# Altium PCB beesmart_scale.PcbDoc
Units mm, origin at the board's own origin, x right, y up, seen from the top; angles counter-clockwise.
Board outline 20 x 50.5 mm, 2 copper layers (Top Layer, Bottom Layer); 16 components, 17 nets, 63 pads, 10 vias.
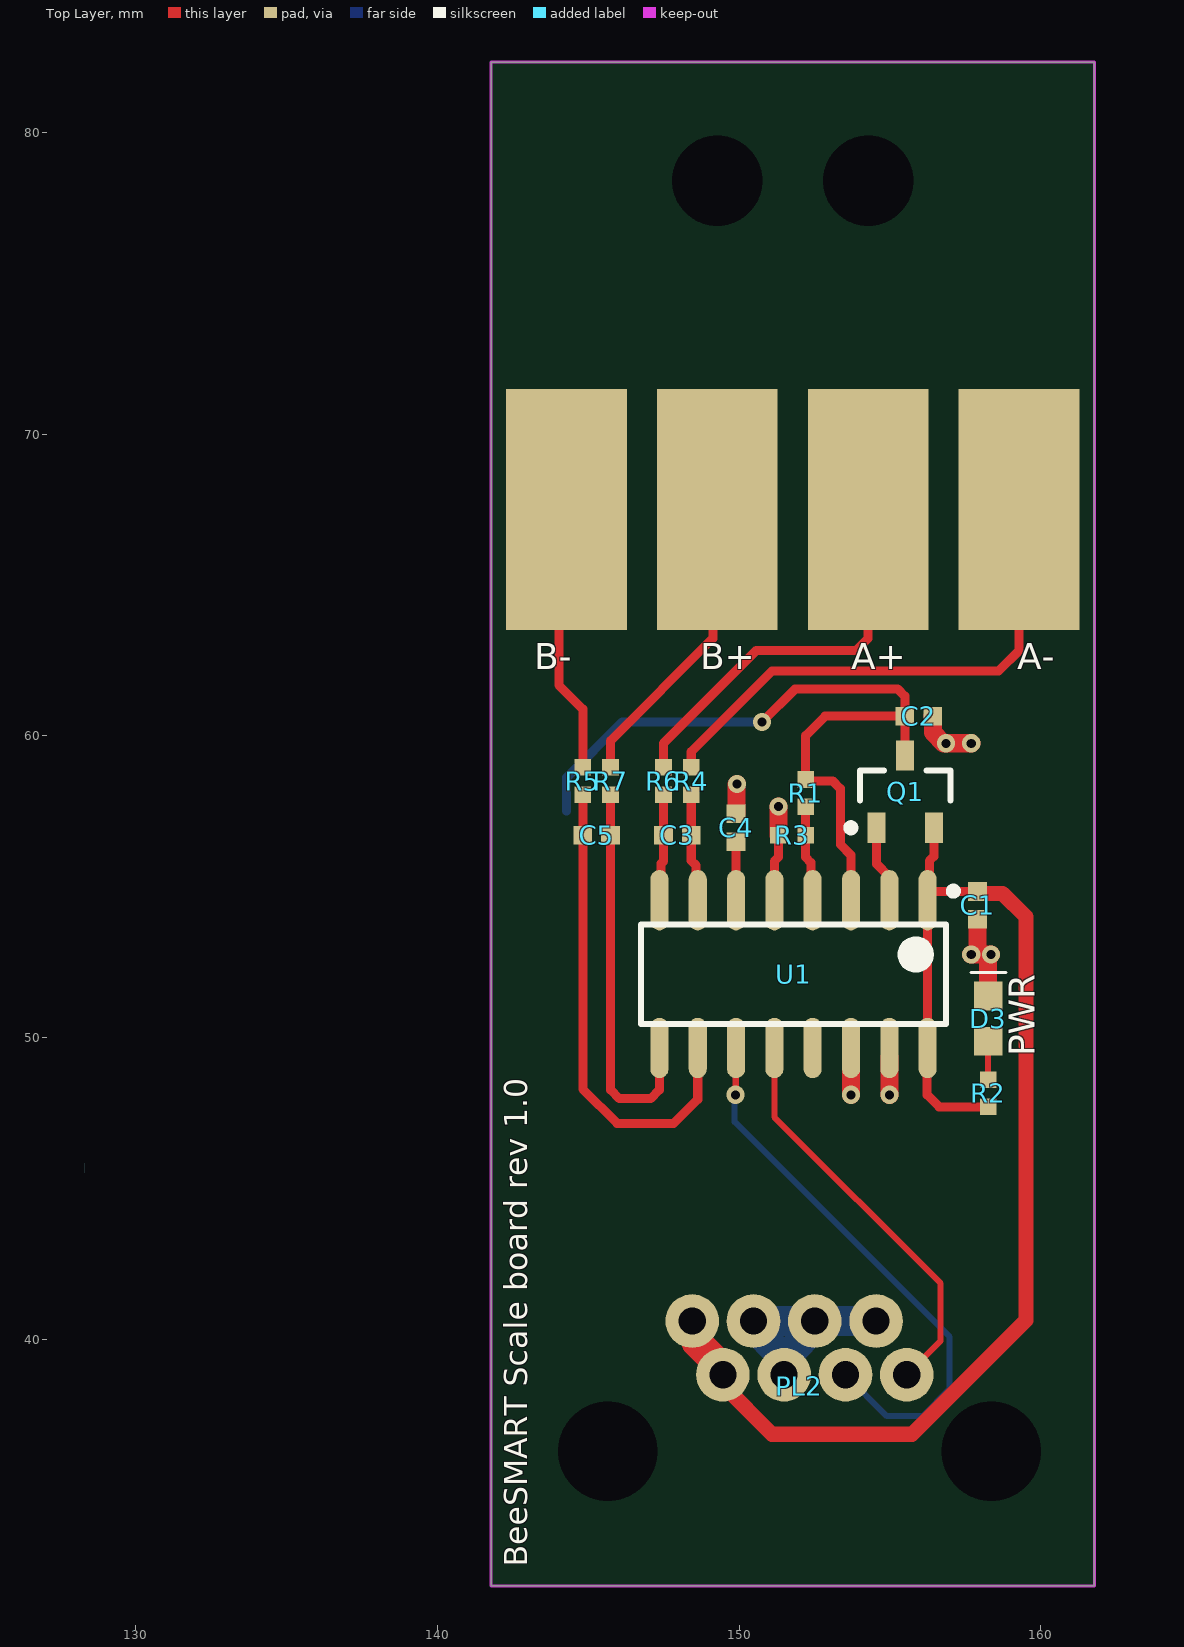
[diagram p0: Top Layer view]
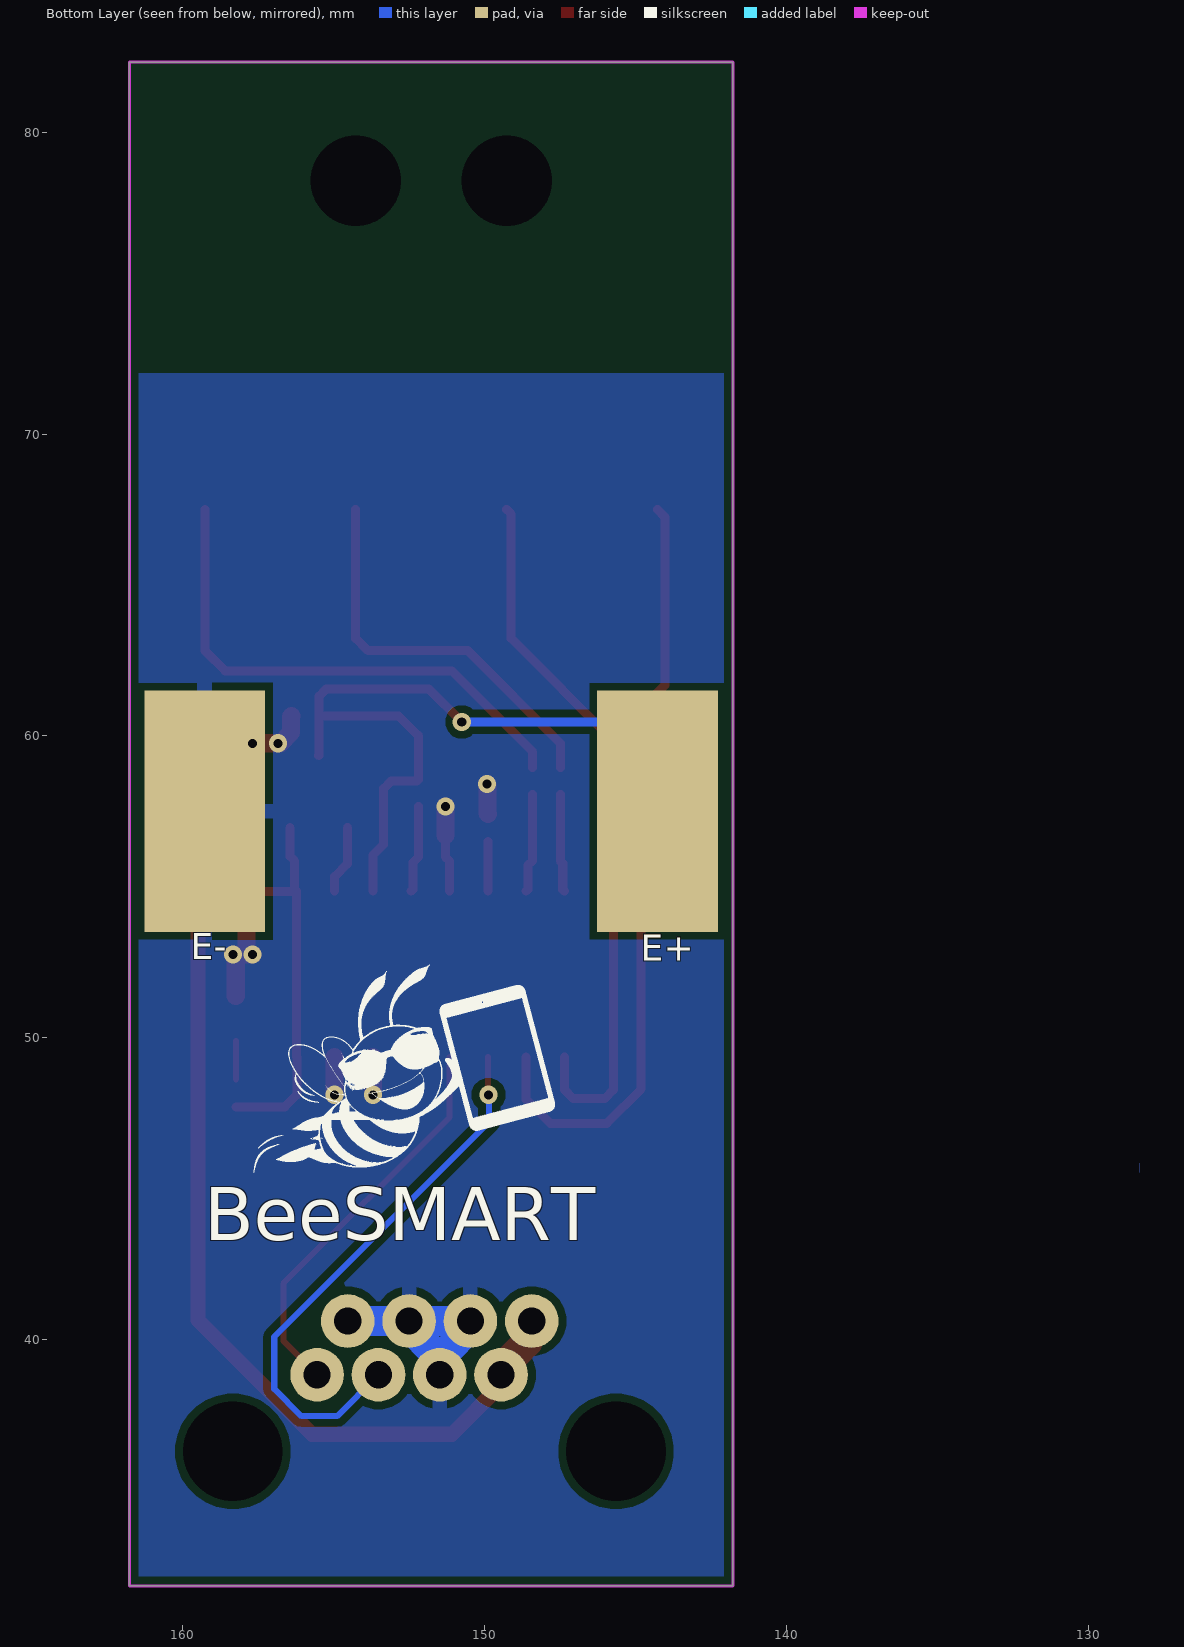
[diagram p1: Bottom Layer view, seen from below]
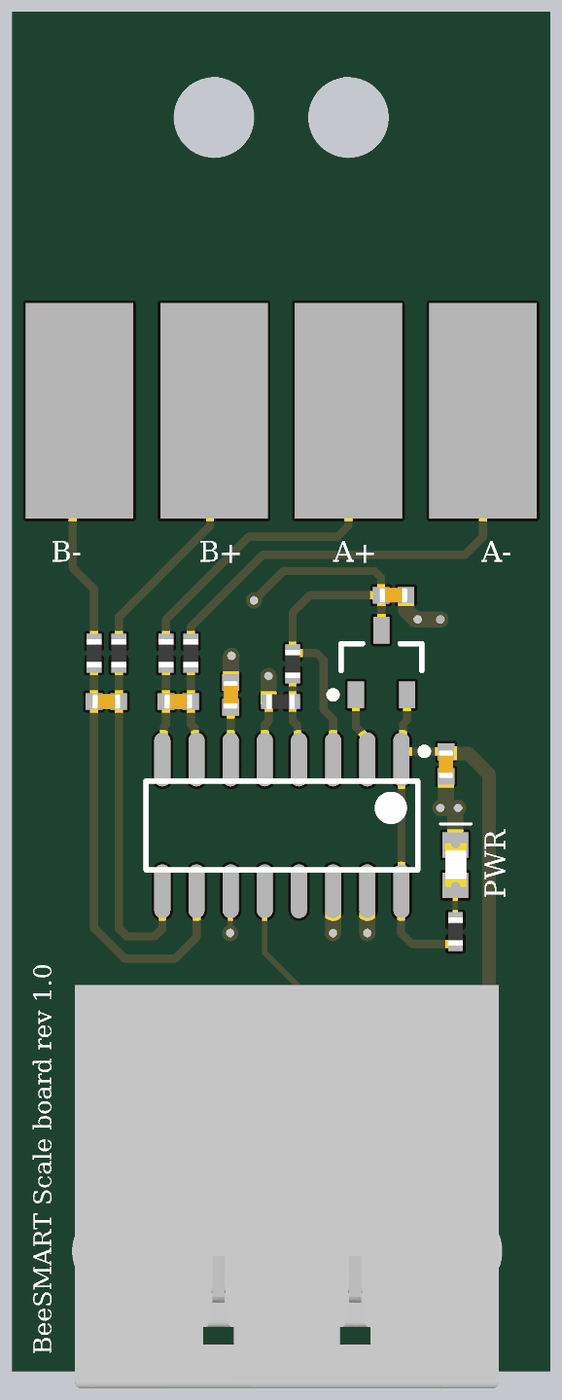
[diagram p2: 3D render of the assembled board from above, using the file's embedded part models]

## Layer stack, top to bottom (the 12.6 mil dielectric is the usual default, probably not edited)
Top Solder: solder mask 0.0102, Solder Resist, Dk 3.5
Top Layer: signal copper 0.0356
Dielectric 1: dielectric 0.32, FR-4, Dk 4.8
Bottom Layer: signal copper 0.0356
Bottom Solder: solder mask 0.0102, Solder Resist, Dk 3.5

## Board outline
141.775,31.825 161.775,31.825 161.775,82.325 141.775,82.325

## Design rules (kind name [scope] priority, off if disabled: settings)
Clearance [All] p1: gap=0.254 ignorepadtopadclearanceinfootprint=FALSE except(0: Arc-Hole Track-Hole SMDPad-Hole THPad-Hole Via-Hole Fill-Hole Poly-Hole Region-Hole Text-Hole; 0.2: Arc-SMDPad Arc-THPad Track-SMDPad Track-THPad SMDPad-SMDPad SMDPad-THPad)
PlaneConnect [All] p1: planeconnectstyle=Relief reliefexpansion=0.508 reliefentries=4 reliefconductorwidth=0.5 reliefairgap=0.254
PolygonConnect PolygonConnect_2 [IsVia] p1: connectstyle=Direct reliefconductorwidth=0.254 reliefentries=4 polygonreliefangle="90 Angle" airgapwidth=0.254
PolygonConnect PolygonConnect_1 [(InNet('VBUS') OR InNet('NetF1_2'))] p2: connectstyle=Direct reliefconductorwidth=0.254 reliefentries=4 polygonreliefangle="90 Angle" airgapwidth=0.254
PolygonConnect [All] p3: connectstyle=Relief reliefconductorwidth=0.5 reliefentries=4 polygonreliefangle="90 Angle" airgapwidth=0.254
RoutingVias [All] p1: holewidth=0.711 width=1.27 viastyle="Through Hole" minholewidth=0.711 minwidth=1.27 maxholewidth=0.711 maxwidth=1.27
SolderMaskExpansion [All] p1: expansion=0.102 istentingtop=FALSE
Width [All] p1: maxlimit=1 minlimit=0.2 preferedwidth=0.25 minimp=50.000000 maximp=50.000000 favimp=50.000000
29 further rules are at their usual default settings.

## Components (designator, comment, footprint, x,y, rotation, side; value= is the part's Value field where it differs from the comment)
C1 "10uF 0402 6V3" CAP_0402 157.9,54.375 r90 top value=10uF
C2 "10uF 0402 6V3" CAP_0402 155.95,60.65 r180 top value=10uF
C3 "0.1uF 0402 10V" CAP_0402 147.95,56.7 r180 top value="100 nF"
C4 "0.1uF 0402 10V" CAP_0402 149.895,56.95 r90 top value="100 nF"
C5 "0.1uF 0402 10V" CAP_0402 145.275,56.7 r0 top value="100 nF"
D3 "GREEN LED 0603" "0603 LED" 151.265,66.627 r270 top
PL2 "RJHSE-5080/R-RJ45R08P-A004" "AMPHENOL RJHSE-5080" 151.998,38.441 r0 top
Q1 "PNP S8550 Transistor" SOT95P245X110-3N 155.5,58.15 r90 top
R1 "20k 0402" RES_0402 152.2,58.1 r270 top value=22k
R2 "1k 0402" RES_0402 158.25,48.15 r270 top value=1k
R3 "8k2 0402 0.1%" RES_0402 151.75,56.7 r0 top value=8k2
R4 "100R 0402" RES_0402 148.41,58.5 r90 top value=100R
R5 "100R 0402" RES_0402 144.815,58.5 r270 top value=100R
R6 "100R 0402" RES_0402 147.49,58.5 r90 top value=100R
R7 "100R 0402" RES_0402 145.735,58.5 r270 top value=100R
U1 "HX711" TSOP127P600X160-16N 151.8,52.1 r270 top

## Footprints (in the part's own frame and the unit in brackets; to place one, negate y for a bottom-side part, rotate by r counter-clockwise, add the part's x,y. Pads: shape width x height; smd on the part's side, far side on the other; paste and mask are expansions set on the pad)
"0603 LED" [mm] "0603 LED"
  rect 0.95x0.95 smd: 1(16.752,6.985) 2(15.252,6.985)
  silkscreen extent 14.48,6.43 14.48,7.57, body extent 15.2,6.61 16.8,7.39, height 0.7
"AMPHENOL RJHSE-5080" [mil] "RJ45 connector"
  round 0 hole 130 unplated: 0(-250,-85) 0(250,-85)
  round 70 hole 35.43: 1(140,15) 2(100,85) 3(60,15) 4(20,85) 5(-20,15) 6(-60,85) 7(-100,15) 8(-140,85)
  body extent -310,-286 310,304, height 521
CAP_0402 [mm] "Chip Capacitor, 2-Leads, 0402, IPC Medium Density"
  rect 0.62x0.62 smd: 1(-0.46,0) 2(0.46,0)
  body extent -0.53,-0.28 0.53,0.28, height 0.4
RES_0402 [mm] "Chip Resistor, 2-Leads, 0402, IPC Medium Density"
  rect 0.55x0.55 smd: 1(-0.45,0) 2(0.45,0)
  body extent -0.53,-0.28 0.53,0.28, height 0.4
SOT95P245X110-3N [mm] "SOT23, 3-Leads, Body 2,90x2,45mm, Pitch 0,95mm, IPC Medium Density"
  rect 1x0.6 smd: 1(-1.2,-0.95) 2(-1.2,0.95) 3(1.2,0)
  silkscreen extent -1.32,-1.5 0.7,1.92, body extent -0.7,-1.5 0.7,1.5, height 1.1
TSOP127P600X160-16N [mm] "TSOP, 16-Leads, Body 9,90x3,90mm, Pitch 1,27mm, IPC Medium Density"
  oval 2x0.6 smd: 1(-2.45,4.445) 2(-2.45,3.175) 3(-2.45,1.905) 4(-2.45,0.635) 5(-2.45,-0.635) 6(-2.45,-1.905) 7(-2.45,-3.175) 8(-2.45,-4.445) 9(2.45,-4.445) 10(2.45,-3.175) 11(2.45,-1.905) 12(2.45,-0.635) 13(2.45,0.635) 14(2.45,1.905) 15(2.45,3.175) 16(2.45,4.445)
  silkscreen extent -2.87,-5.05 1.65,5.42, body extent -2.05,-5.05 2.05,5.05, height 1.6

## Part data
C1 C2: library part CMP-00011-3, "10uF 20% 0402 6V3 X6S", Current Rating=-, Tolerance=20%, Voltage=6V3
C3 C4 C5: library part CMP-00101-1, "0.1uF 0402 10V X7R 10%", Tolerance="10 %", Voltage="10 V"
D3: library part CMP-008-0000-1, "SMD GREEN WATER CLEAR", Mfg. Part Number=APT1608SGC
PL2: library part CMP-003-0022-0.1, "CONN MOD JACK 8P8C R/A UNSHLD", Colour=Black, Contact Resistance=20mR, Current Rating=1.5A, Flammability Rating="UL94 V-0", Max Operating Temperature=85°C, Max Voltage Rating (AC)=125V, Min Operating Temperature=-55°C, Package Quantity=36
Q1: library part CMP-014-0022-0.0, "S8550", Part no.=C105432
R1: library part CMP-001-0026-3, "RES SMD 22K OHM 1% 1/16W 0402", Case/Package=0402, Mfg. Part Number=RMCF0402FT22K0, Power=1/16W, Tolerance=1%
R2: library part CMP-001-0025-3, "RES SMD 1K OHM 1% 1/16W 0402", Case/Package=0402, Mfg. Part Number=CRG0402F1K0, Power=1/16W, Tolerance=1%
R3: library part CMP-001-0038-2, "TE CONNECTIVITY / NEOHM         CPF0402B8K2E1             SMD Chip Resistor, Thin Film, 8.2 kohm, 25 V, 0402 [1005 Metric], 63 mW,  0.1%, CPF Series", Case/Package=0402, Power="1/16 W", Tolerance="0.1 %"
R4 R5 R6 R7: library part CMP-001-0001-5, "100R 1% 0402 63mW", Case/Package=0402, Power=63mW, Tolerance=1%
U1: library part CMP-00183-2, "24-Bit Analog-to-Digital Converter (ADC) for Weigh Scales", Part no=C6705483

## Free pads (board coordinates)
  rect 4x8 smd: 1(144.275,67.5) 2(149.275,67.5) 3(154.275,67.5) 4(159.275,67.5)
  round 0 hole 3 unplated: 2(149.275,78.4) 2(154.275,78.4)
  rect 4x8 smd far side: 5(144.275,57.5) 6(159.275,57.5)

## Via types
v1: diameter 0.6, hole 0.3, Top Layer to Bottom Layer, tented both sides, 10 vias

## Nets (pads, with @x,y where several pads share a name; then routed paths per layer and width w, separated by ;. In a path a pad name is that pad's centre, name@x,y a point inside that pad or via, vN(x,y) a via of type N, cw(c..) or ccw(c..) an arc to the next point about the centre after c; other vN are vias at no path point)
3V3: C1.2 PL2.7 PL2.8 Q1.1 R2.2 U1.1 U1.16 | length 42.9
  Top Layer w0.3: Q1.1 156.45,56 156.302,55.852 156.302,54.907 U1.1@156.245,54.85 ; C1.2 157.892,54.843 156.252,54.843 U1.1@156.245,54.85 ; R2.2 156.627,47.7 156.227,48.1 156.227,49.332 156.245,49.35 U1.1@156.245,54.85
  Top Layer w0.5: PL2.7 149.458,38.476 151.084,36.85 155.725,36.85 159.5,40.625 159.5,54 158.725,54.775 157.96,54.775 C1.2
  Top Layer w1: PL2.8 148.59,40.451 148.59,39.9 149.458,39.033 PL2.7
A+: pad.3 R6.2 | length 13.3
  Top Layer w0.3: R6.2 147.49,59.75 150.565,62.825 153.874,62.825 154.275,63.226 pad.3
A-: pad.4 R4.2 | length 17.4
  Top Layer w0.3: R4.2 148.41,59.47 151.09,62.15 158.6,62.15 159.275,62.825 pad.4
B+: pad.2@149.275,67.5 R7.1 | length 10
  Top Layer w0.3: R7.1 145.735,59.835 149.126,63.226 149.126,67.351 pad.2@149.275,67.5
B-: pad.1 R5.1 | length 9
  Top Layer w0.3: pad.1 144.025,67.25 144.025,61.675 144.815,60.885 R5.1
E+: C2.2 pad.5 Q1.3 R1.1 U1.3 | length 25.4
  Top Layer w0.3: v1(150.76,60.46) 151.85,61.55 155.253,61.55 155.49,61.313 C2.2 ; U1.3@153.705,54.85 153.705,56.045 153.35,56.4 153.35,58.25 153.1,58.5 152.25,58.5 R1.1 152.2,60 152.85,60.65 C2.2 ; Q1.3 155.495,59.355 155.495,60.645 C2.2
  Bottom Layer w0.3: pad.5 144.275,58.61 146.125,60.46 v1(150.76,60.46)
E-: C1.1 C2.1 C4.2 D3.2 pad.6 PL2.2 PL2.4 PL2.5 PL2.6 R3.1 U1.5 U1.14 U1.15 | length 20.1
  Top Layer w0.3: U1.5@151.165,54.85 151.165,55.84 151.3,55.975 R3.1
  Top Layer w0.6: C4.2 149.905,57.42 149.905,58.38 v1(149.925,58.4) ; R3.1 v1(151.3,57.65) ; v1(153.7,48.1) 153.705,48.105 U1.14@153.705,49.35 ; v1(154.975,48.1) U1.15@154.975,49.35 ; C2.1 156.42,60.64 156.42,60.101 156.771,59.75 v1(156.85,59.75) v1(157.69,59.75) ; v1(157.69,52.75) 158.019,52.75 ; C1.1 157.9,52.869 158.019,52.75 ; D3.2 158.25,52.652 v1(158.348,52.75) 158.019,52.75
  Bottom Layer w1: PL2.2 PL2.4 ; PL2.4 152.506,40.389 151.638,39.522 151.638,38.971 PL2.5 151.341,38.971 151.341,39.522 150.474,40.389 PL2.6 PL2.4
IO1: PL2.3 U1.11 | length 18.4
  Top Layer w0.2: v1(149.875,48.1) 149.885,48.11 149.885,49.34 U1.11@149.895,49.35
  Bottom Layer w0.2: v1(149.875,48.1) 149.85,48.075 149.85,47.2 156.975,40.075 156.975,38.35 156.075,37.45 154.894,37.45 PL2.3
IO3: PL2.1 U1.12 | length 13.3
  Top Layer w0.2: U1.12@151.165,49.35 151.165,47.36 156.675,41.85 156.675,39.943 PL2.1
NetC3_1: C3.1 R4.1 U1.7 | length 3.3
  Top Layer w0.3: R4.1 C3.1 148.41,55.859 148.568,55.701 148.568,54.907 U1.7@148.625,54.85
NetC3_2: C3.2 R6.1 U1.8 | length 3.3
  Top Layer w0.3: U1.8@147.355,54.85 147.412,54.907 147.412,55.762 147.49,55.84 C3.2 R6.1
NetC4_1: C4.1 U1.6 | length 1.6
  Top Layer w0.3: U1.6@149.895,54.85 C4.1
NetC5_1: C5.1 R5.2 U1.10 | length 15.8
  Top Layer w0.3: R5.2 C5.1 144.815,48.285 145.95,47.15 147.825,47.15 148.625,47.95 U1.10@148.625,49.35
NetC5_2: C5.2 R7.2 U1.9 | length 12.7
  Top Layer w0.3: R7.2 C5.2 145.735,48.265 146.025,47.975 147.065,47.975 147.355,48.265 U1.9@147.355,49.35
NetD3_1: D3.1 R2.1 | length 1.3
  Top Layer w0.2: R2.1 D3.1
NetQ1_2: Q1.2 U1.2 | length 2.3
  Top Layer w0.3: Q1.2 154.55,55.756 154.975,55.331 U1.2@154.975,54.85
NetR1_2: R1.2 R3.2 U1.4 | length 2.9
  Top Layer w0.3: R1.2 R3.2 152.2,55.975 152.378,55.797 152.378,54.907 U1.4@152.435,54.85
pads on no net: PL2.0 U1.13

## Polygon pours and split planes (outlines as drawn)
E- on Bottom Layer "E-_L02_P000" (solid, remove dead copper, pour order 0): 140.875,74.8 141.2,75.125 166.15,75.125 166.15,31.575 161.425,26.85 136.125,26.85

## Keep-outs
Keep-Out Layer:
  the board outline again, w0.1

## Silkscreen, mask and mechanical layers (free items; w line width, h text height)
Top Overlay:
  text "B-" at 143.213,61.9 h1.5
  text "B+" at 148.713,61.9 h1.5
  text "A+" at 153.713,61.9 h1.5
  text "A-" at 159.213,61.9 h1.5
  text "PWR" at 160.1,49.375 h1.5 r90
  text "BeeSMART Scale board rev 1.0" at 143.225,32.45 h1.3 r90
Bottom Overlay:
  drawing of 29 lines, arcs and shapes, not listed
  text "E-" at 159.75,52.3 h1.5
  text "E+" at 144.825,52.25 h1.5
  text "BeeSMART" at 159.298,42.698 h3
Outline:
  the board outline again, w0.1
